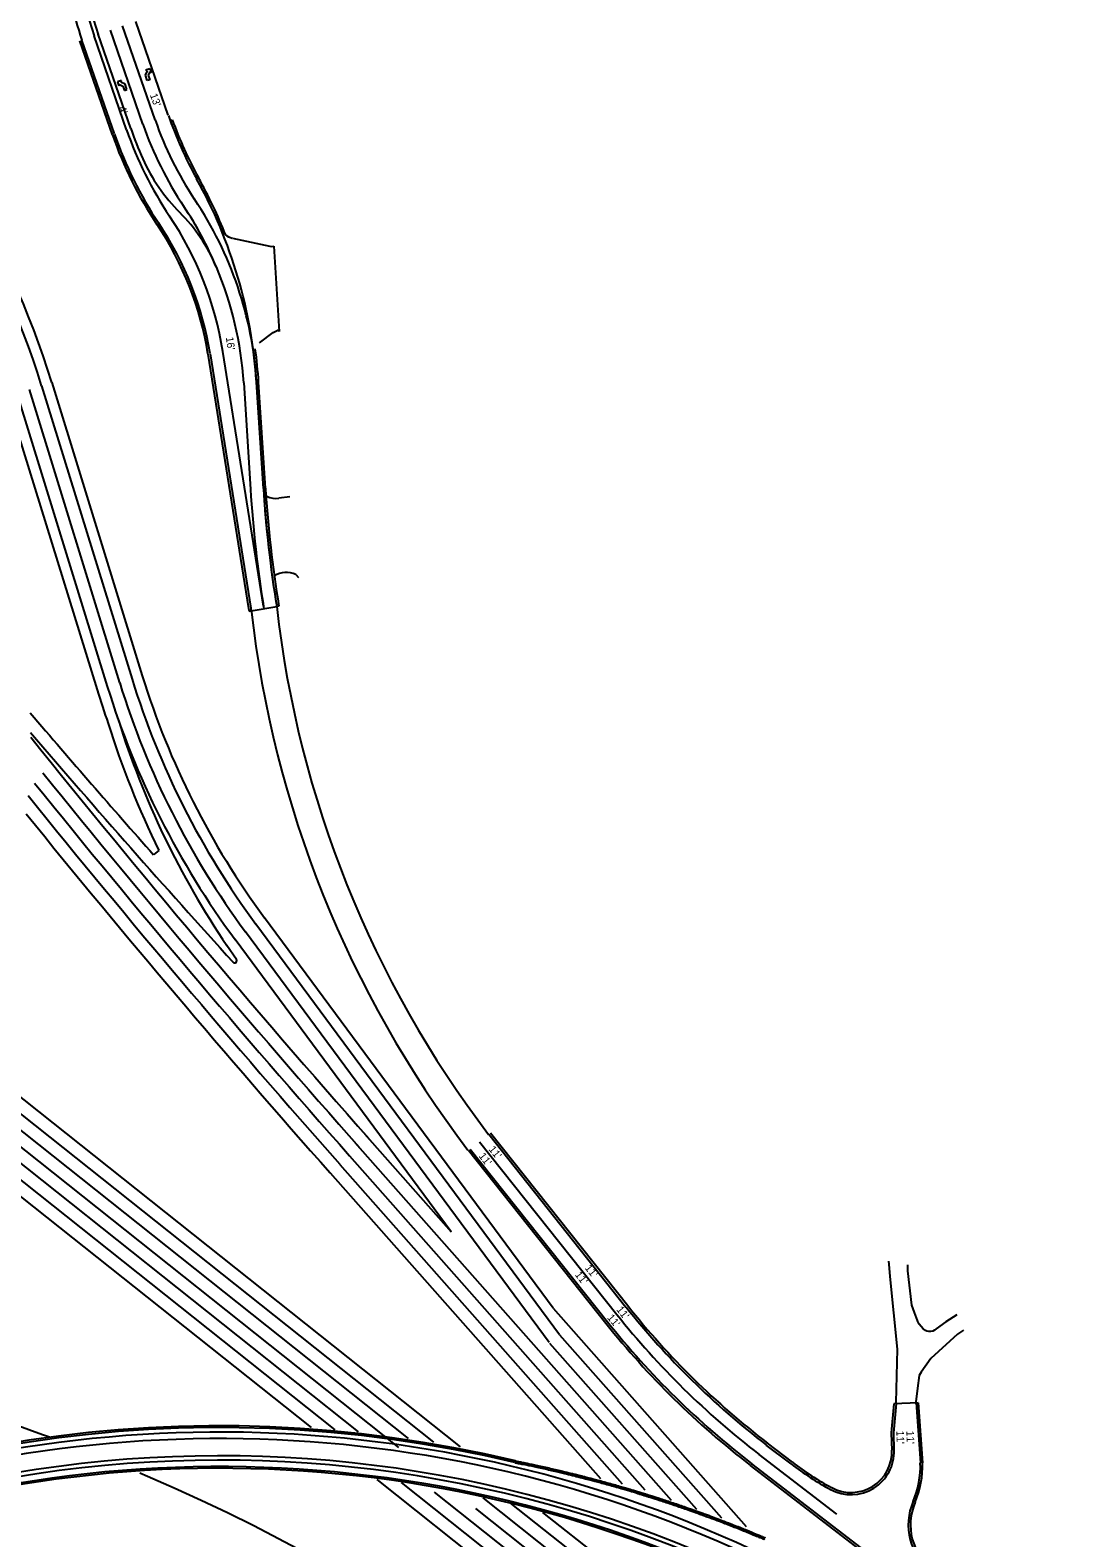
# Model space of a CAD drawing. Extents: x -5665 to 1997148, y 4 to 812485.
# Drawn here: x 1969306 to 1970265, y 797701 to 799100 of the extents above; entities that cross this region are included whole.
import ezdxf

# ---------------------------------------------------------------- set-up
doc = ezdxf.new("R2010")
doc.units = 0
for name, color, linetype in [('BR_CONCRETE', 7, 'Continuous'), ('RD_EX_RailRoad', 7, 'Continuous'), ('RD_EX_Road', 7, 'Continuous'), ('RD_PD_ALT1_TrvlWay', 7, 'Continuous'), ('RD_PD_Driveway', 7, 'Continuous'), ('RD_PD_Final_LnLine', 7, 'Continuous'), ('RD_PD_Final_TrvlWay', 7, 'Continuous'), ('RD_PD_PaintMed', 7, 'Continuous'), ('RD_PD_PaveShd', 7, 'Continuous'), ('RD_SHT_TX', 7, 'Continuous')]:
    doc.layers.add(name, color=color, linetype=linetype)

msp = doc.modelspace()

# ---------------------------------------------------------------- linework, layer by layer
at = {"layer": 'BR_CONCRETE'}
for centre, radius, start, end in [((1969482, 796626.9), 1177.6, 76.5407, 163.611), ((1969482, 796626.9), 1176, 76.5391, 163.611), ((1969482, 796626.9), 1140, 57.2466, 163.611), ((1969482, 796626.9), 1138.4, 56.954, 163.611), ((1969812.2, 797747.6), 10, 75.8374, 75.8965), ((1969814.7, 797757.3), 1.63, 75.8965, 75.9046), ((1969812.2, 797747.6), 11.6, 75.8374, 75.8965), ((1969870.2, 797731.4), 10, 72.8844, 72.9435), ((1969873.2, 797741), 1.63, 72.9435, 72.9516), ((1969870.2, 797731.4), 11.6, 72.8844, 72.9435), ((1969927.4, 797712.2), 10, 69.9315, 69.9905), ((1969930.9, 797721.6), 1.63, 69.9905, 69.9986), ((1969927.4, 797712.2), 11.6, 69.9315, 69.9905), ((1969987.6, 797699.2), 1.63, 67.0375, 67.0457)]:
    msp.add_arc(centre, radius, start, end, dxfattribs=at)
for points in [[(1969755.7, 797770.6), (1969756, 797770.5), (1969756.2, 797770.5), (1969756.7, 797770.4), (1969757.1, 797770.3), (1969758, 797770.1), (1969759.8, 797769.7), (1969764.2, 797768.9), (1969772.8, 797767.1), (1969785.2, 797764.4), (1969797.5, 797761.5), (1969806.1, 797759.5), (1969810.4, 797758.4), (1969812.2, 797757.9), (1969813.1, 797757.7), (1969813.4, 797757.6), (1969814, 797757.5), (1969814.3, 797757.4), (1969814.7, 797757.3)], [(1969756.1, 797772.1), (1969756.6, 797772), (1969757.1, 797771.9), (1969758.3, 797771.7), (1969758.9, 797771.6), (1969760.8, 797771.2), (1969764.5, 797770.5), (1969773.2, 797768.7), (1969785.5, 797766), (1969797.9, 797763.1), (1969806.5, 797761), (1969810.1, 797760.1), (1969812, 797759.7), (1969812.6, 797759.5), (1969813.5, 797759.3), (1969813.8, 797759.2), (1969814.4, 797759), (1969814.7, 797759), (1969815, 797758.9)], [(1969814.7, 797757.3), (1969815, 797757.2), (1969815.3, 797757.2), (1969815.9, 797757), (1969816.2, 797756.9), (1969817.1, 797756.7), (1969818.9, 797756.2), (1969823.2, 797755.1), (1969831.8, 797752.9), (1969844, 797749.6), (1969856.2, 797746.1), (1969864.7, 797743.6), (1969868.9, 797742.3), (1969870.7, 797741.7), (1969871.6, 797741.4), (1969871.9, 797741.3), (1969872.6, 797741.2), (1969872.9, 797741.1), (1969873.2, 797741)], [(1969815.1, 797758.9), (1969815.7, 797758.7), (1969816.3, 797758.6), (1969817.5, 797758.3), (1969818.1, 797758.1), (1969820, 797757.6), (1969823.6, 797756.7), (1969832.2, 797754.5), (1969844.5, 797751.1), (1969856.6, 797747.6), (1969865.1, 797745.1), (1969868.8, 797744), (1969870.6, 797743.5), (1969871.2, 797743.3), (1969872.1, 797743), (1969872.4, 797742.9), (1969873, 797742.7), (1969873.3, 797742.6), (1969873.6, 797742.5)], [(1969873.2, 797741), (1969873.5, 797740.9), (1969873.8, 797740.8), (1969874.4, 797740.6), (1969874.7, 797740.5), (1969875.6, 797740.2), (1969877.4, 797739.7), (1969881.6, 797738.3), (1969890.1, 797735.7), (1969902.1, 797731.7), (1969914.1, 797727.6), (1969922.5, 797724.6), (1969926.7, 797723.1), (1969928.5, 797722.5), (1969929.4, 797722.1), (1969929.7, 797722), (1969930.3, 797721.8), (1969930.6, 797721.7), (1969930.9, 797721.6)], [(1969873.6, 797742.5), (1969874.2, 797742.3), (1969874.8, 797742.2), (1969876.1, 797741.8), (1969876.7, 797741.6), (1969878.5, 797741), (1969882.1, 797739.9), (1969890.6, 797737.2), (1969902.7, 797733.2), (1969914.7, 797729.1), (1969923.1, 797726.1), (1969926.6, 797724.9), (1969928.4, 797724.2), (1969929, 797724), (1969929.9, 797723.7), (1969930.2, 797723.6), (1969930.8, 797723.3), (1969931.1, 797723.2), (1969931.4, 797723.1)], [(1969930.9, 797721.6), (1969931.2, 797721.5), (1969931.5, 797721.4), (1969932, 797721.2), (1969932.3, 797721.1), (1969933.2, 797720.7), (1969935, 797720.1), (1969939.2, 797718.5), (1969947.5, 797715.4), (1969959.4, 797710.8), (1969971.2, 797706.1), (1969979.4, 797702.7), (1969983.5, 797701), (1969985.3, 797700.2), (1969986.1, 797699.8), (1969986.4, 797699.7), (1969987, 797699.5), (1969987.3, 797699.4), (1969987.6, 797699.2)], [(1969931.4, 797723.1), (1969932, 797722.9), (1969932.6, 797722.7), (1969933.8, 797722.3), (1969934.4, 797722), (1969936.2, 797721.4), (1969939.8, 797720), (1969948.1, 797716.9), (1969960, 797712.3), (1969971.8, 797707.6), (1969980, 797704.2), (1969983.5, 797702.7), (1969985.3, 797702), (1969985.9, 797701.7), (1969986.8, 797701.3), (1969987.1, 797701.2), (1969987.6, 797701), (1969987.9, 797700.9), (1969988.2, 797700.7)]]:
    msp.add_open_spline(points, degree=3, dxfattribs=at)
at = {"layer": 'RD_EX_RailRoad'}
for points in [[(1969323.6, 797794.1), (1969317.1, 797796.5), (1969291.6, 797805.7), (1969266.1, 797814.4), (1969240.4, 797822.8), (1969223.2, 797828.1), (1969169.9, 797843.7), (1969146.6, 797849.7)], [(1969602.4, 797664), (1969598.5, 797666.3), (1969576, 797678.9), (1969513.3, 797711.8), (1969488.9, 797723.8), (1969464.2, 797735.5), (1969439.4, 797746.8), (1969414.4, 797757.7), (1969407.4, 797760.7)]]:
    msp.add_lwpolyline(points, dxfattribs=at)
at = {"layer": 'RD_EX_Road'}
for points in [[(1970109.6, 797826.3), (1970110.8, 797876), (1970104.2, 797943.4), (1970103.2, 797954.8), (1970103, 797957.6)], [(1970165.9, 797907.7), (1970155.9, 797901.4), (1970146.8, 797894.7), (1970145.4, 797893.5), (1970143.7, 797892.7), (1970142, 797892.3), (1970140.1, 797892.3), (1970138.3, 797892.6), (1970137.1, 797893.1), (1970134.9, 797894.8), (1970132.9, 797896.9), (1970131.2, 797899.2), (1970129.8, 797901.7), (1970129.5, 797902.5), (1970126.6, 797909.9), (1970124.2, 797916.7), (1970120.7, 797948.5), (1970120.5, 797954.1)], [(1970172.1, 797893.4), (1970166.7, 797889.8), (1970141.9, 797867.2), (1970132.9, 797854.4), (1970131.2, 797851.3), (1970129.6, 797839.7), (1970128.1, 797827.1), (1970128, 797825.3)]]:
    msp.add_lwpolyline(points, dxfattribs=at)
for radius in [1016.2, 992.2]:
    msp.add_arc((1970520.5, 798676.5), radius, 186.4376, 217.2948, dxfattribs=at)
at = {"layer": 'RD_PD_ALT1_TrvlWay'}
for p, q in [((1969316.1, 798770.4), (1969400.1, 798498)), ((1969293.2, 798763.3), (1969377.1, 798491)), ((1969797.2, 797889.2), (1969515.1, 798270.5)), ((1969497, 798237.8), (1969488.2, 798250.6)), ((1969696.6, 797984.7), (1969495.8, 798256.2)), ((1969256.4, 798126.2), (1969680.1, 797789.6)), ((1969239.7, 798078.2), (1969588.5, 797801.1)), ((1969616, 798075.9), (1969696.6, 797984.7)), ((1969731.4, 798075.4), (1969858.8, 797915)), ((1969714.2, 798061.7), (1969841.6, 797901.3)), ((1969593, 798047.5), (1969855.4, 797750.8)), ((1969797.2, 797889.2), (1969947.5, 797719.2)), ((1970109.6, 797825.4), (1970107.2, 797798.1)), ((1970130.2, 797826.1), (1970107.6, 797825.3)), ((1970128.2, 797826), (1970132.2, 797770.3)), ((1970107.2, 797798.1), (1970107.7, 797782.2)), ((1970012.1, 797769.3), (1969989.1, 797786.9)), ((1970244.1, 797563.5), (1969975.7, 797769.5)), ((1969650.1, 797752.2), (1969798.3, 797634.4)), ((1969751.1, 797733.2), (1969828.2, 797672))]:
    msp.add_line(p, q, dxfattribs=at)
for centre, radius, start, end in [((1968568.8, 798540.1), 782, 17.1278, 46.9958), ((1970124.5, 798721.3), 782, 197.1278, 216.4938), ((1970124.5, 798721.3), 758, 197.1278, 216.4938), ((1970139.4, 798693.2), 787.3, 197.2297, 214.2064), ((1976946, 804998.5), 10063.6, 220.60625, 222.22617), ((1977158.2, 804739.2), 10064, 218.71888, 221.49377), ((1977158.2, 804739.2), 10100, 218.95037, 221.49377), ((1969495.4, 798236.5), 2, 220.3184, 40.3184), ((1970445.2, 798381.1), 749, 218.48, 232.4907), ((1970445.2, 798381.1), 771, 218.48, 232.4907), ((1969482, 796626.9), 1166, 65.0802, 163.611), ((1969482, 796626.9), 1150, 31.3716, 163.611), ((1970067.8, 797780.8), 40, 241.7796, 2.0052), ((1970176.5, 797983.5), 270, 232.4907, 241.7796), ((1970049.2, 797767.4), 83, 336.731, 2.0052), ((1970176, 797712.9), 55, 156.731, 232.4907)]:
    msp.add_arc(centre, radius, start, end, dxfattribs=at)
at = {"layer": 'RD_PD_Driveway'}
for p, q in [((1969493.3, 798907.3), (1969528.2, 798899.8)), ((1969528.2, 798899.8), (1969529.3, 798899.6)), ((1969529.3, 798899.6), (1969531.7, 798899.8)), ((1969531.7, 798899.8), (1969536.8, 798820.8)), ((1969518.4, 798810.1), (1969531.2, 798819.8)), ((1969531.2, 798819.8), (1969534.8, 798821.7)), ((1969535.8, 798821.6), (1969534.8, 798821.7)), ((1969536.6, 798821.1), (1969535.8, 798821.6)), ((1969536.8, 798820.8), (1969536.6, 798821.1)), ((1969524.6, 798668.2), (1969525.6, 798667.7)), ((1969546.7, 798667.3), (1969536.5, 798666)), ((1969552.3, 798595.1), (1969554.7, 798592.2))]:
    msp.add_line(p, q, dxfattribs=at)
for centre, radius, start, end in [((1969496.4, 798922), 15, 202.5345, 257.8806), ((1969534, 798685.8), 20, 245.0108, 277.1826), ((1969543.4, 798575.7), 21.3, 65.5808, 121.6889)]:
    msp.add_arc(centre, radius, start, end, dxfattribs=at)
at = {"layer": 'RD_PD_Final_LnLine'}
for p, q in [((1969421.6, 799017.1), (1969391.4, 799104.4)), ((1969410.2, 799013.2), (1969380.1, 799100.5)), ((1969304.7, 798766.9), (1969388.6, 798494.5)), ((1969787.5, 797882), (1969505.4, 798263.3)), ((1969252.3, 798114.2), (1969656.5, 797793)), ((1969247.9, 798102.3), (1969647.7, 797784.7)), ((1969244, 798090.1), (1969610.2, 797799.2)), ((1969607, 798067.9), (1969900.7, 797735.8)), ((1969722.8, 798068.5), (1969850.2, 797908.2)), ((1969602, 798055.5), (1969876.2, 797745.4)), ((1969787.8, 797881.6), (1969924.3, 797727.3)), ((1970054.6, 797722.8), (1969982.4, 797778.2)), ((1969680.7, 797743.2), (1969805.8, 797643.8)), ((1969725.9, 797737.9), (1969820.7, 797662.6)), ((1969719.2, 797727.9), (1969813.3, 797653.2))]:
    msp.add_line(p, q, dxfattribs=at)
for centre, radius, start, end in [((1969725, 799121.9), 333, 199.0518, 213.7837), ((1969725, 799121.9), 321, 199.0518, 213.7837), ((1969171.5, 798751.6), 333, 22.8293, 33.7837), ((1969171.5, 798751.6), 345, 3.6771, 33.7837), ((1970124.5, 798721.3), 770, 197.1278, 216.4938), ((1977158.2, 804739.2), 10076, 218.90631, 221.49377), ((1977158.2, 804739.2), 10088, 218.92103, 221.49377), ((1970445.2, 798381.1), 760, 218.48, 232.4907)]:
    msp.add_arc(centre, radius, start, end, dxfattribs=at)
at = {"layer": 'RD_PD_Final_TrvlWay'}
for p, q in [((1969433.8, 799021.4), (1969403.7, 799108.6)), ((1969383.8, 799004.1), (1969353.6, 799091.3)), ((1969472.6, 798800.1), (1969510.4, 798563.8)), ((1969522.1, 798675.1), (1969515.7, 798773.7)), ((1969510.8, 798561.4), (1969534.5, 798565.3))]:
    msp.add_line(p, q, dxfattribs=at)
for centre, radius, start, end in [((1969665.1, 799198.9), 329.6, 185.7857, 199.0518), ((1969780.3, 799141), 366.5, 199.0518, 209.1352), ((1969725, 799121.9), 361, 199.0518, 213.7837), ((1969069.9, 798745), 446.7, 3.6771, 29.1352), ((1969171.5, 798751.6), 305, 9.1587, 33.7837), ((1970664.6, 798748.6), 1144.9, 183.6771, 187.9875), ((1970664.6, 798748.6), 1144.9, 183.6771, 189.2135), ((1970664.6, 798748.6), 1168.9, 189.0946, 189.2135)]:
    msp.add_arc(centre, radius, start, end, dxfattribs=at)
at = {"layer": 'RD_PD_PaintMed'}
for p, q in [((1969395.1, 799008), (1969365, 799095.3)), ((1969398.9, 799009.3), (1969368.7, 799096.6)), ((1969522.3, 798565.7), (1969484.4, 798802)), ((1969503.8, 798772.9), (1969510.1, 798674.4))]:
    msp.add_line(p, q, dxfattribs=at)
for centre, radius, start, end in [((1969665.1, 799198.9), 317.6, 178.558, 199.0518), ((1969665.1, 799198.9), 313.6, 178.558, 199.0518), ((1969725, 799121.9), 349, 199.0518, 213.7837), ((1969725, 799121.9), 345, 199.0518, 204.0911), ((1969562, 799049), 166.4, 204.0911, 225.0596), ((1969171.5, 798751.6), 317, 9.1587, 33.7837), ((1969333, 798819.6), 157.7, 22.8293, 45.0596), ((1969171.5, 798751.6), 333, 3.6771, 22.8293), ((1970664.6, 798748.6), 1156.9, 183.6771, 189.2135)]:
    msp.add_arc(centre, radius, start, end, dxfattribs=at)
at = {"layer": 'RD_PD_PaveShd'}
for p, q in [((1969381.9, 799003.4), (1969351.7, 799090.7)), ((1969435.7, 799016.6), (1969437.4, 799017.2)), ((1969470.6, 798799.8), (1969508.4, 798563.5)), ((1969325.7, 798773.3), (1969409.6, 798501)), ((1969524.1, 798675.3), (1969517.7, 798773.8)), ((1969283.6, 798760.4), (1969367.6, 798488)), ((1969508.8, 798561.1), (1969510.8, 798561.4)), ((1969536.5, 798565.6), (1969534.5, 798565.3)), ((1969425.1, 798338.9), (1969420.5, 798335.1)), ((1969791.3, 797913.9), (1969523.1, 798276.4)), ((1969260.6, 798138.2), (1969704.8, 797785.3)), ((1969733, 798076.6), (1969860.4, 797916.3)), ((1969234.8, 798066.7), (1969566.4, 797803.3)), ((1969712.6, 798060.5), (1969840.1, 797900.1)), ((1969584, 798039.6), (1969835, 797755.8)), ((1969791.3, 797913.9), (1969970.5, 797711.3)), ((1970107.6, 797825.3), (1970105.2, 797798.3)), ((1970130.2, 797826.1), (1970134.2, 797770.4)), ((1970013.3, 797770.9), (1969990.3, 797788.5)), ((1970105.2, 797798), (1970105.7, 797782.2)), ((1970242.9, 797561.9), (1969974.5, 797767.9)), ((1969627.5, 797754.8), (1969790.9, 797625)), ((1969781.4, 797724.4), (1969835.6, 797681.4))]:
    msp.add_line(p, q, dxfattribs=at)
for centre, radius, start, end in [((1968568.8, 798540.1), 792, 17.1278, 46.9958), ((1969780.3, 799141), 364.5, 199.8469, 209.1352), ((1969725, 799121.9), 363, 199.0518, 213.7837), ((1969069.9, 798745), 448.7, 21.5926, 29.1352), ((1969171.5, 798751.6), 303, 9.1587, 33.7837), ((1969069.9, 798745), 448.7, 3.6771, 7.6498), ((1970664.6, 798748.6), 1142.9, 183.6771, 189.2135), ((1970664.6, 798748.6), 1170.9, 189.0946, 189.2135), ((1970124.5, 798721.3), 792, 197.1278, 199.5026), ((1970124.5, 798721.3), 748, 197.1278, 216.4938), ((1976946, 804998.5), 10052, 220.5279, 221.52305), ((1970139.4, 798693.2), 797.3, 197.244, 206.3828), ((1977158.2, 804739.2), 10112, 219.01886, 221.49377), ((1970445.2, 798381.1), 747, 218.48, 232.4907), ((1970445.2, 798381.1), 773, 218.48, 232.4907), ((1969482, 796626.9), 1172, 65.0633, 163.611), ((1970067.8, 797780.8), 38, 241.7796, 2.0052), ((1969482, 796626.9), 1146, 31.3716, 163.611), ((1970176.5, 797983.5), 268, 232.4907, 241.7796), ((1970049.2, 797767.4), 85, 336.731, 2.0295), ((1970176, 797712.9), 53, 156.731, 232.4907)]:
    msp.add_arc(centre, radius, start, end, dxfattribs=at)
at = {"layer": 'RD_SHT_TX'}
for p, q in [((1969412.5, 799058.7), (1969414.4, 799062.8)), ((1969413, 799063.5), (1969416.8, 799064.8)), ((1969414.4, 799062.8), (1969413, 799063.5)), ((1969416.6, 799061.7), (1969415.1, 799058.6)), ((1969418.1, 799061), (1969416.6, 799061.7)), ((1969416.8, 799064.8), (1969418.1, 799061)), ((1969390.3, 799053.8), (1969386.5, 799052.4)), ((1969386.5, 799052.4), (1969387.8, 799048.7)), ((1969387.8, 799048.7), (1969388.5, 799050.1)), ((1969388.5, 799050.1), (1969391.6, 799048.6)), ((1969389.6, 799052.3), (1969390.3, 799053.8)), ((1969393.6, 799050.3), (1969389.6, 799052.3)), ((1969391.6, 799048.6), (1969393.1, 799044.5)), ((1969395.3, 799045.3), (1969393.6, 799050.3)), ((1969414.2, 799053.7), (1969412.5, 799058.7)), ((1969416.5, 799054.5), (1969414.2, 799053.7)), ((1969415.1, 799058.6), (1969416.5, 799054.5)), ((1969393.1, 799044.5), (1969395.3, 799045.3))]:
    msp.add_line(p, q, dxfattribs=at)

# ---------------------------------------------------------------- texts
for s, rotation, p in [("13'", 290.1655, (1969416.6, 799040.3)), ("4'", 289.0518, (1969387.4, 799028.5)), ("16'", 278.3209, (1969487.2, 798815.2)), ("11'", 307.533, (1969721.7, 798055.1)), ("11'", 308.6467, (1969730.9, 798061.3)), ("11'", 307.533, (1969811, 797944.9)), ("11'", 308.6467, (1969820.2, 797951.1)), ("11'", 308.2407, (1969849.5, 797912.5)), ("11'", 310.1671, (1969840.9, 797904.9)), ("11'", 271.8034, (1970109.9, 797800.1)), ("11'", 271.8034, (1970119.2, 797800))]:
    msp.add_text(s, height=7, rotation=rotation, dxfattribs=at).set_placement(p)

doc.saveas('drawing.dxf')
